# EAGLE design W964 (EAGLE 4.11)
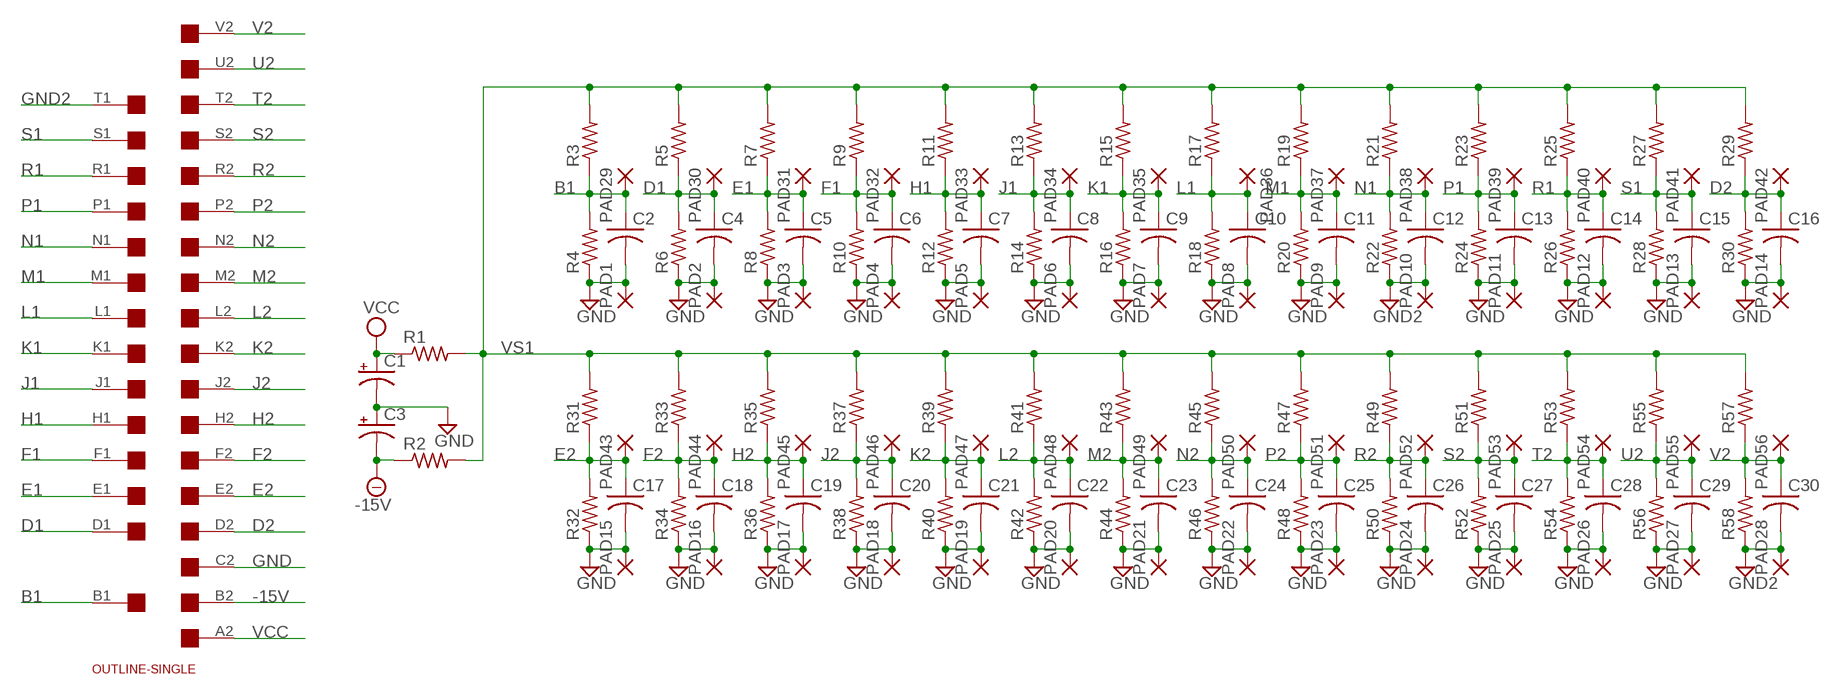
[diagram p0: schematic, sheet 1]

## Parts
C1  CPOL-USE22-6AXIAL  [E22-6]
C2  C-US050-025X075  [C050-025X075]
C3  CPOL-USE22-6AXIAL  [E22-6]
C4  C-US050-025X075  [C050-025X075]
C5  C-US050-025X075  [C050-025X075]
C6  C-US050-025X075  [C050-025X075]
C7  C-US050-025X075  [C050-025X075]
C8  C-US050-025X075  [C050-025X075]
C9  C-US050-025X075  [C050-025X075]
C10  C-US050-025X075  [C050-025X075]
C11  C-US050-025X075  [C050-025X075]
C12  C-US050-025X075  [C050-025X075]
C13  C-US050-025X075  [C050-025X075]
C14  C-US050-025X075  [C050-025X075]
C15  C-US050-025X075  [C050-025X075]
C16  C-US050-025X075  [C050-025X075]
C17  C-US050-025X075  [C050-025X075]
C18  C-US050-025X075  [C050-025X075]
C19  C-US050-025X075  [C050-025X075]
C20  C-US050-025X075  [C050-025X075]
C21  C-US050-025X075  [C050-025X075]
C22  C-US050-025X075  [C050-025X075]
C23  C-US050-025X075  [C050-025X075]
C24  C-US050-025X075  [C050-025X075]
C25  C-US050-025X075  [C050-025X075]
C26  C-US050-025X075  [C050-025X075]
C27  C-US050-025X075  [C050-025X075]
C28  C-US050-025X075  [C050-025X075]
C29  C-US050-025X075  [C050-025X075]
C30  C-US050-025X075  [C050-025X075]
PAD1  1,6/0,9  [1,6/0,9]
PAD2  1,6/0,9  [1,6/0,9]
PAD3  1,6/0,9  [1,6/0,9]
PAD4  1,6/0,9  [1,6/0,9]
PAD5  1,6/0,9  [1,6/0,9]
PAD6  1,6/0,9  [1,6/0,9]
PAD7  1,6/0,9  [1,6/0,9]
PAD8  1,6/0,9  [1,6/0,9]
PAD9  1,6/0,9  [1,6/0,9]
PAD10  1,6/0,9  [1,6/0,9]
PAD11  1,6/0,9  [1,6/0,9]
PAD12  1,6/0,9  [1,6/0,9]
PAD13  1,6/0,9  [1,6/0,9]
PAD14  1,6/0,9  [1,6/0,9]
PAD15  1,6/0,9  [1,6/0,9]
PAD16  1,6/0,9  [1,6/0,9]
PAD17  1,6/0,9  [1,6/0,9]
PAD18  1,6/0,9  [1,6/0,9]
PAD19  1,6/0,9  [1,6/0,9]
PAD20  1,6/0,9  [1,6/0,9]
PAD21  1,6/0,9  [1,6/0,9]
PAD22  1,6/0,9  [1,6/0,9]
PAD23  1,6/0,9  [1,6/0,9]
PAD24  1,6/0,9  [1,6/0,9]
PAD25  1,6/0,9  [1,6/0,9]
PAD26  1,6/0,9  [1,6/0,9]
PAD27  1,6/0,9  [1,6/0,9]
PAD28  1,6/0,9  [1,6/0,9]
PAD29  1,6/0,9  [1,6/0,9]
PAD30  1,6/0,9  [1,6/0,9]
PAD31  1,6/0,9  [1,6/0,9]
PAD32  1,6/0,9  [1,6/0,9]
PAD33  1,6/0,9  [1,6/0,9]
PAD34  1,6/0,9  [1,6/0,9]
PAD35  1,6/0,9  [1,6/0,9]
PAD36  1,6/0,9  [1,6/0,9]
PAD37  1,6/0,9  [1,6/0,9]
PAD38  1,6/0,9  [1,6/0,9]
PAD39  1,6/0,9  [1,6/0,9]
PAD40  1,6/0,9  [1,6/0,9]
PAD41  1,6/0,9  [1,6/0,9]
PAD42  1,6/0,9  [1,6/0,9]
PAD43  1,6/0,9  [1,6/0,9]
PAD44  1,6/0,9  [1,6/0,9]
PAD45  1,6/0,9  [1,6/0,9]
PAD46  1,6/0,9  [1,6/0,9]
PAD47  1,6/0,9  [1,6/0,9]
PAD48  1,6/0,9  [1,6/0,9]
PAD49  1,6/0,9  [1,6/0,9]
PAD50  1,6/0,9  [1,6/0,9]
PAD51  1,6/0,9  [1,6/0,9]
PAD52  1,6/0,9  [1,6/0,9]
PAD53  1,6/0,9  [1,6/0,9]
PAD54  1,6/0,9  [1,6/0,9]
PAD55  1,6/0,9  [1,6/0,9]
PAD56  1,6/0,9  [1,6/0,9]
R1  R-US_0207/10  [0207/10]
R2  R-US_0207/10  [0207/10]
R3  R-US_0207/10  [0207/10]
R4  R-US_0207/10  [0207/10]
R5  R-US_0207/10  [0207/10]
R6  R-US_0207/10  [0207/10]
R7  R-US_0207/10  [0207/10]
R8  R-US_0207/10  [0207/10]
R9  R-US_0207/10  [0207/10]
R10  R-US_0207/10  [0207/10]
R11  R-US_0207/10  [0207/10]
R12  R-US_0207/10  [0207/10]
R13  R-US_0207/10  [0207/10]
R14  R-US_0207/10  [0207/10]
R15  R-US_0207/10  [0207/10]
R16  R-US_0207/10  [0207/10]
R17  R-US_0207/10  [0207/10]
R18  R-US_0207/10  [0207/10]
R19  R-US_0207/10  [0207/10]
R20  R-US_0207/10  [0207/10]
R21  R-US_0207/10  [0207/10]
R22  R-US_0207/10  [0207/10]
R23  R-US_0207/10  [0207/10]
R24  R-US_0207/10  [0207/10]
R25  R-US_0207/10  [0207/10]
R26  R-US_0207/10  [0207/10]
R27  R-US_0207/10  [0207/10]
R28  R-US_0207/10  [0207/10]
R29  R-US_0207/10  [0207/10]
R30  R-US_0207/10  [0207/10]
R31  R-US_0207/10  [0207/10]
R32  R-US_0207/10  [0207/10]
R33  R-US_0207/10  [0207/10]
R34  R-US_0207/10  [0207/10]
R35  R-US_0207/10  [0207/10]
R36  R-US_0207/10  [0207/10]
R37  R-US_0207/10  [0207/10]
R38  R-US_0207/10  [0207/10]
R39  R-US_0207/10  [0207/10]
R40  R-US_0207/10  [0207/10]
R41  R-US_0207/10  [0207/10]
R42  R-US_0207/10  [0207/10]
R43  R-US_0207/10  [0207/10]
R44  R-US_0207/10  [0207/10]
R45  R-US_0207/10  [0207/10]
R46  R-US_0207/10  [0207/10]
R47  R-US_0207/10  [0207/10]
R48  R-US_0207/10  [0207/10]
R49  R-US_0207/10  [0207/10]
R50  R-US_0207/10  [0207/10]
R51  R-US_0207/10  [0207/10]
R52  R-US_0207/10  [0207/10]
R53  R-US_0207/10  [0207/10]
R54  R-US_0207/10  [0207/10]
R55  R-US_0207/10  [0207/10]
R56  R-US_0207/10  [0207/10]
R57  R-US_0207/10  [0207/10]
R58  R-US_0207/10  [0207/10]
U$1  EDGE-2CONNECTOR  [EDGE-CON2]
U$2  OUTLINE-SINGLE  [SINGLE]

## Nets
-15V [power]: C3.- R2.1 U$1.B2
B1: C2.1 PAD29.1(P) R3.1 R4.2 U$1.B1
D1: C4.1 PAD30.1(P) R5.1 R6.2 U$1.D1
D2: C16.1 PAD42.1(P) R29.1 R30.2 U$1.D2
E1: C5.1 PAD31.1(P) R7.1 R8.2 U$1.E1
E2: C17.1 PAD43.1(P) R31.1 R32.2 U$1.E2
F1: C6.1 PAD32.1(P) R9.1 R10.2 U$1.F1
F2: C18.1 PAD44.1(P) R33.1 R34.2 U$1.F2
GND [power]: C1.- C2.2 C3.+ C4.2 C5.2 C6.2 C7.2 C8.2 C9.2 C10.2 C11.2 C13.2 C14.2 C15.2 C16.2 C17.2 C18.2 C19.2 C20.2 C21.2 C22.2 C23.2 C24.2 C25.2 C26.2 C27.2 C28.2 C29.2 PAD1.1(P) PAD2.1(P) PAD3.1(P) PAD4.1(P) PAD5.1(P) PAD6.1(P) PAD7.1(P) PAD8.1(P) PAD9.1(P) PAD11.1(P) PAD12.1(P) PAD13.1(P) PAD14.1(P) PAD15.1(P) PAD16.1(P) PAD17.1(P) PAD18.1(P) PAD19.1(P) PAD20.1(P) PAD21.1(P) PAD22.1(P) PAD23.1(P) PAD24.1(P) PAD25.1(P) PAD26.1(P) PAD27.1(P) R4.1 R6.1 R8.1 R10.1 R12.1 R14.1 R16.1 R18.1 R20.1 R24.1 R26.1 R28.1 R30.1 R32.1 R34.1 R36.1 R38.1 R40.1 R42.1 R44.1 R46.1 R48.1 R50.1 R52.1 R54.1 R56.1 U$1.C2
GND2 [power]: C12.2 C30.2 PAD10.1(P) PAD28.1(P) R22.1 R58.1 U$1.T1
H1: C7.1 PAD33.1(P) R11.1 R12.2 U$1.H1
H2: C19.1 PAD45.1(P) R35.1 R36.2 U$1.H2
J1: C8.1 PAD34.1(P) R13.1 R14.2 U$1.J1
J2: C20.1 PAD46.1(P) R37.1 R38.2 U$1.J2
K1: C9.1 PAD35.1(P) R15.1 R16.2 U$1.K1
K2: C21.1 PAD47.1(P) R39.1 R40.2 U$1.K2
L1: C10.1 PAD36.1(P) R17.1 R18.2 U$1.L1
L2: C22.1 PAD48.1(P) R41.1 R42.2 U$1.L2
M1: C11.1 PAD37.1(P) R19.1 R20.2 U$1.M1
M2: C23.1 PAD49.1(P) R43.1 R44.2 U$1.M2
N1: C12.1 PAD38.1(P) R21.1 R22.2 U$1.N1
N2: C24.1 PAD50.1(P) R45.1 R46.2 U$1.N2
P1: C13.1 PAD39.1(P) R23.1 R24.2 U$1.P1
P2: C25.1 PAD51.1(P) R47.1 R48.2 U$1.P2
R1: C14.1 PAD40.1(P) R25.1 R26.2 U$1.R1
R2: C26.1 PAD52.1(P) R49.1 R50.2 U$1.R2
S1: C15.1 PAD41.1(P) R27.1 R28.2 U$1.S1
S2: C27.1 PAD53.1(P) R51.1 R52.2 U$1.S2
T2: C28.1 PAD54.1(P) R53.1 R54.2 U$1.T2
U2: C29.1 PAD55.1(P) R55.1 R56.2 U$1.U2
V2: C30.1 PAD56.1(P) R57.1 R58.2 U$1.V2
VCC [power]: C1.+ R1.1 U$1.A2
VS1: R1.2 R2.2 R3.2 R5.2 R7.2 R9.2 R11.2 R13.2 R15.2 R17.2 R19.2 R21.2 R23.2 R25.2 R27.2 R29.2 R31.2 R33.2 R35.2 R37.2 R39.2 R41.2 R43.2 R45.2 R47.2 R49.2 R51.2 R53.2 R55.2 R57.2
Unconnected: U$1.A1 U$1.C1 U$1.U1 U$1.V1

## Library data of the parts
C1 C3 = rcl:CPOL-US: POLARIZED CAPACITOR, American symbol
C2 C4-C30 = rcl:C-US: CAPACITOR, American symbol
PAD1-PAD56 = wirepad:1,6/0,9: THROUGH-HOLE PAD
R1-R58 = rcl:R-US_: RESISTOR, American symbol
U$1 = dec-con:EDGE-2: Double-Sided DEC edge connector.
U$2 = dec-con:OUTLINE-*: Board outlines for DEC boards.

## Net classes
1 power: width 0.508 mm

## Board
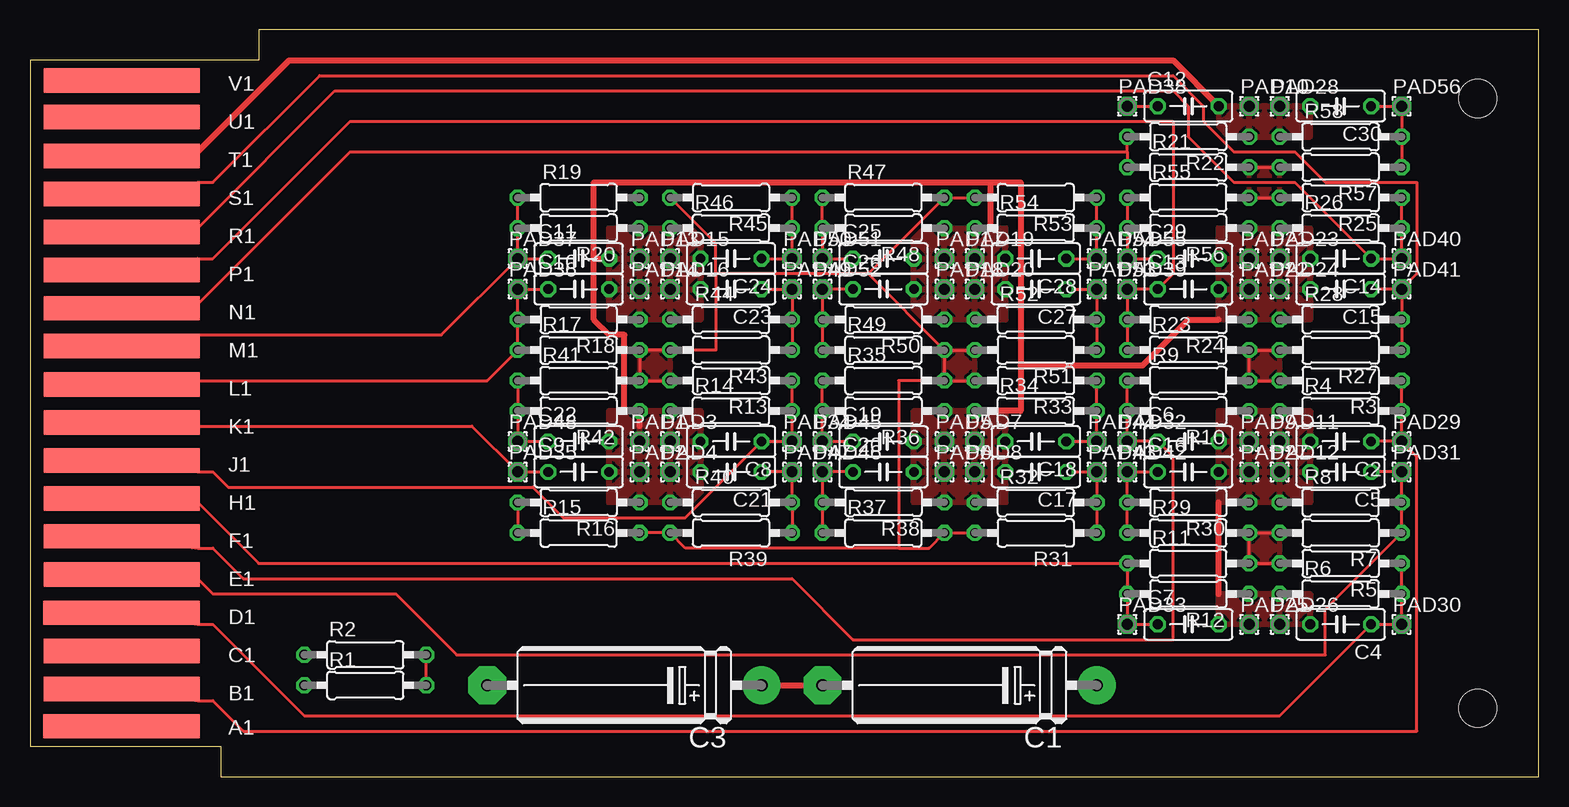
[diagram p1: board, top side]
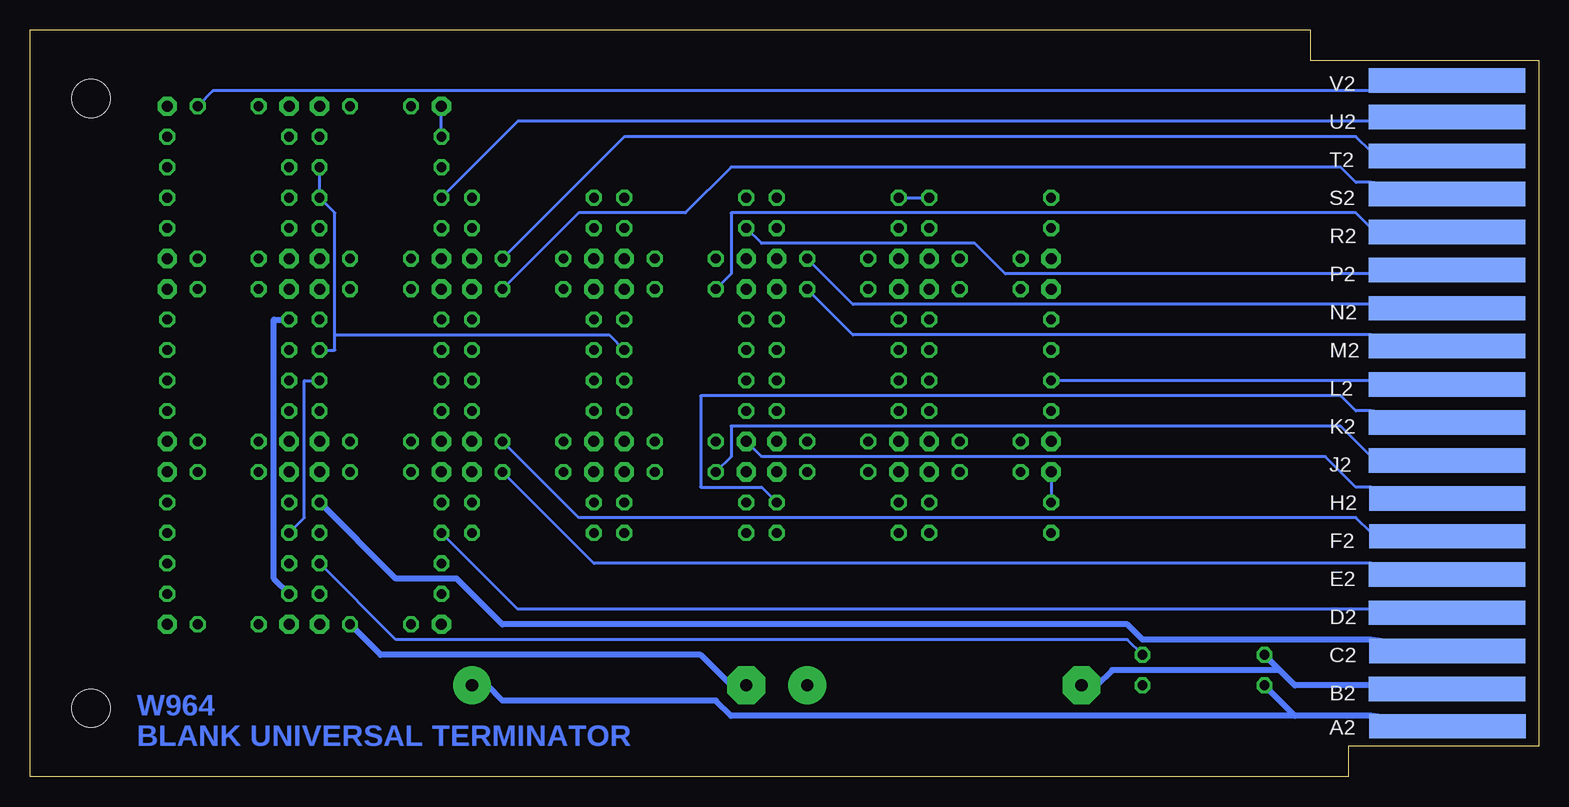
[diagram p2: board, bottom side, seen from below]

Size 125.73 x 62.23 mm. Coordinates in mm from the lower left corner, seen from the top.
Copper layers (1*16): Top 0.035mm / dielectric 1.5mm / Bottom 0.035mm
Design rules "10mils": minimum track width 10mil, minimum drill 24mil, track to track 10mil, track to pad 10mil, pad to pad 10mil, via to via 10mil, smd to smd 10mil, copper to edge 25mil, drill to drill 10mil, minimum pad ring 10mil, minimum via ring 8mil, stop-mask expansion 0mil, vias tented up to drill 0mil, thermal gap 10mil

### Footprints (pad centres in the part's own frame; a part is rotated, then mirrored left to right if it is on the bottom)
E22-6 = drill 1.016 pad 3.15 round: + -11.43,0 | drill 1.016 pad 3.15 octagon: - 11.43,0
C050-025X075 = drill 0.813 octagon: 1 -2.54,0; 2 2.54,0
1,6/0,9 = drill 0.914 pad 1.6 octagon: 1 0,0
0207/10 = drill 0.813 octagon: 1 -5.08,0; 2 5.08,0
EDGE-CON2 = smd 13.017 x 2.032: A1 7.633,4.207; B1 7.639,7.327; C1 7.636,10.489; D1 7.633,13.665; E1 7.642,16.84; F1 7.642,20.041; H1 7.642,23.19; J1 7.642,26.34; K1 7.642,29.515; L1 7.642,32.69; M1 7.642,35.89; N1 7.642,39.04; P1 7.642,42.24; R1 7.642,45.39; S1 7.642,48.565; T1 7.642,51.74; U1 7.642,54.966; V1 7.642,58.026 | smd 13.017 x 2.032 bottom: A2 7.614,4.207; B2 7.642,7.328; C2 7.617,10.49; D2 7.642,13.665; E2 7.642,16.84; F2 7.617,20.041; H2 7.617,23.19; J2 7.642,26.34; K2 7.642,29.515; L2 7.642,32.69; M2 7.642,35.89; N2 7.642,39.04; P2 7.642,42.24; R2 7.642,45.39; S2 7.642,48.565; T2 7.642,51.74; U2 7.642,54.966; V2 7.642,58.026
SINGLE = hole 3.175: 120.65,56.515; 120.65,5.715

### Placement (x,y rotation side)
C1  77.47,7.62 180 top
C2  109.22,27.94 180 top
C3  49.53,7.62 180 top
C4  109.22,12.7 180 top
C5  109.22,25.4 180 top
C6  96.52,27.94 0 top
C7  96.52,12.7 0 top
C8  58.42,27.94 180 top
C9  45.72,25.4 0 top
C10  45.72,40.64 0 top
C11  45.72,43.18 0 top
C12  96.52,55.88 0 top
C13  96.52,40.64 0 top
C14  109.22,43.18 180 top
C15  109.22,40.64 180 top
C16  96.52,25.4 0 top
C17  83.82,25.4 180 top
C18  83.82,27.94 180 top
C19  71.12,27.94 0 top
C20  71.12,25.4 0 top
C21  58.42,25.4 180 top
C22  45.72,27.94 0 top
C23  58.42,40.64 180 top
C24  58.42,43.18 180 top
C25  71.12,43.18 0 top
C26  71.12,40.64 0 top
C27  83.82,40.64 180 top
C28  83.82,43.18 180 top
C29  96.52,43.18 0 top
C30  109.22,55.88 180 top
PAD1  50.8,27.94 0 top
PAD2  50.8,25.4 0 top
PAD3  53.34,27.94 0 top
PAD4  53.34,25.4 0 top
PAD5  76.2,27.94 0 top
PAD6  76.2,25.4 0 top
PAD7  78.74,27.94 0 top
PAD8  78.74,25.4 0 top
PAD9  101.6,27.94 0 top
PAD10  101.6,55.88 0 top
PAD11  104.14,27.94 0 top
PAD12  104.14,25.4 0 top
PAD13  50.8,43.18 0 top
PAD14  50.8,40.64 0 top
PAD15  53.34,43.18 0 top
PAD16  53.34,40.64 0 top
PAD17  76.2,43.18 0 top
PAD18  76.2,40.64 0 top
PAD19  78.74,43.18 0 top
PAD20  78.74,40.64 0 top
PAD21  101.6,43.18 0 top
PAD22  101.6,40.64 0 top
PAD23  104.14,43.18 0 top
PAD24  104.14,40.64 0 top
PAD25  101.6,12.7 0 top
PAD26  104.14,12.7 0 top
PAD27  101.6,25.4 0 top
PAD28  104.14,55.88 0 top
PAD29  114.3,27.94 0 top
PAD30  114.3,12.7 0 top
PAD31  114.3,25.4 0 top
PAD32  91.44,27.94 0 top
PAD33  91.44,12.7 0 top
PAD34  63.5,27.94 0 top
PAD35  40.64,25.4 0 top
PAD36  40.64,40.64 0 top
PAD37  40.64,43.18 0 top
PAD38  91.44,55.88 0 top
PAD39  91.44,40.64 0 top
PAD40  114.3,43.18 0 top
PAD41  114.3,40.64 0 top
PAD42  91.44,25.4 0 top
PAD43  88.9,25.4 0 top
PAD44  88.9,27.94 0 top
PAD45  66.04,27.94 0 top
PAD46  66.04,25.4 0 top
PAD47  63.5,25.4 0 top
PAD48  40.64,27.94 0 top
PAD49  63.5,40.64 0 top
PAD50  63.5,43.18 0 top
PAD51  66.04,43.18 0 top
PAD52  66.04,40.64 0 top
PAD53  88.9,40.64 0 top
PAD54  88.9,43.18 0 top
PAD55  91.44,43.18 0 top
PAD56  114.3,55.88 0 top
R1  27.94,7.62 0 top
R2  27.94,10.16 0 top
R3  109.22,33.02 180 top
R4  109.22,30.48 0 top
R5  109.22,17.78 180 top
R6  109.22,15.24 0 top
R7  109.22,20.32 180 top
R8  109.22,22.86 0 top
R9  96.52,33.02 0 top
R10  96.52,30.48 180 top
R11  96.52,17.78 0 top
R12  96.52,15.24 180 top
R13  58.42,33.02 180 top
R14  58.42,30.48 0 top
R15  45.72,20.32 0 top
R16  45.72,22.86 180 top
R17  45.72,35.56 0 top
R18  45.72,38.1 180 top
R19  45.72,48.26 0 top
R20  45.72,45.72 180 top
R21  96.52,50.8 0 top
R22  96.52,53.34 180 top
R23  96.52,35.56 0 top
R24  96.52,38.1 180 top
R25  109.22,48.26 180 top
R26  109.22,45.72 0 top
R27  109.22,35.56 180 top
R28  109.22,38.1 0 top
R29  96.52,20.32 0 top
R30  96.52,22.86 180 top
R31  83.82,20.32 180 top
R32  83.82,22.86 0 top
R33  83.82,33.02 180 top
R34  83.82,30.48 0 top
R35  71.12,33.02 0 top
R36  71.12,30.48 180 top
R37  71.12,20.32 0 top
R38  71.12,22.86 180 top
R39  58.42,20.32 180 top
R40  58.42,22.86 0 top
R41  45.72,33.02 0 top
R42  45.72,30.48 180 top
R43  58.42,35.56 180 top
R44  58.42,38.1 0 top
R45  58.42,48.26 180 top
R46  58.42,45.72 0 top
R47  71.12,48.26 0 top
R48  71.12,45.72 180 top
R49  71.12,35.56 0 top
R50  71.12,38.1 180 top
R51  83.82,35.56 180 top
R52  83.82,38.1 0 top
R53  83.82,48.26 180 top
R54  83.82,45.72 0 top
R55  96.52,48.26 0 top
R56  96.52,45.72 180 top
R57  109.22,50.8 180 top
R58  109.22,53.34 0 top
U$1  0,0 0 top
U$2  0,0 0 top

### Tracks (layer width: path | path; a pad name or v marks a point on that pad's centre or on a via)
-15V
  Bottom 0.508: 21.59,8.89 20.32,7.62 13.97,7.62 U$1.B2 | 21.59,8.89 R2.1 | 21.59,8.89 35.56,8.89 36.83,7.62 C3.-
B1
  Top 0.254: R3.1 R4.2 PAD29.1 | PAD29.1 C2.1 | PAD29.1 115.57,26.67 115.57,3.81 17.78,3.81 15.24,6.35 13.97,6.35 U$1.B1
D1
  Top 0.254: R5.1 R6.2 PAD30.1 C4.1 104.14,5.08 22.86,5.08 15.24,12.7 13.97,12.7 U$1.D1
D2
  Top 0.254: R29.1 R30.2 PAD42.1 C16.1
  Bottom 0.254: R29.1 85.09,13.97 13.97,13.97 U$1.D2
E1
  Top 0.254: C5.1 PAD31.1 R8.2 R7.1 107.95,13.97 107.95,10.16 35.56,10.16 30.48,15.24 15.24,15.24 13.97,16.51 U$1.E1
E2
  Top 0.254: R31.1 R32.2 PAD43.1 C17.1
  Bottom 0.254: C17.1 78.74,17.78 13.97,17.78 U$1.E2
F1
  Top 0.254: R9.1 R10.2 PAD32.1 C6.1 95.25,26.67 95.25,11.43 68.58,11.43 63.5,16.51 17.78,16.51 15.24,19.05 13.97,19.05 U$1.F1
F2
  Top 0.254: R33.1 R34.2 PAD44.1 C18.1
  Bottom 0.254: C18.1 80.01,21.59 15.24,21.59 13.97,20.32 U$1.F2
GND
  Top 0.508: 99.06,15.24 99.06,22.86 | C3.+ C1.- | 46.99,43.18 46.99,38.1 48.26,36.83 49.53,36.83 49.53,30.48 R42.1 50.8,29.21 | 46.99,43.18 46.99,49.53 80.01,49.53 | 80.01,49.53 80.01,45.72 | 46.99,43.18 C11.2 | 80.01,49.53 82.55,49.53 82.55,34.29 | 82.55,34.29 92.71,34.29 96.52,38.1 99.06,38.1 | 82.55,34.29 82.55,30.48 R34.1
  Bottom 0.508: R6.1 105.41,16.51 105.41,38.1 R28.1 | C7.2 96.52,10.16 69.85,10.16 67.31,7.62 C1.- | R30.1 95.25,16.51 90.17,16.51 86.36,12.7 34.29,12.7 33.02,11.43 13.97,11.43 U$1.C2
  pour Top: 48.26,30.48 55.88,30.48 55.88,22.86 48.26,22.86
  pour Top: 48.26,45.72 55.88,45.72 55.88,38.1 48.26,38.1
  pour Top: 73.66,45.72 81.28,45.72 81.28,38.1 73.66,38.1
  pour Top: 73.66,30.48 81.28,30.48 81.28,22.86 73.66,22.86
  pour Top: 99.06,30.48 106.68,30.48 106.68,22.86 99.06,22.86
  pour Top: 99.06,45.72 106.68,45.72 106.68,38.1 99.06,38.1
  pour Top: 99.06,12.7 99.06,15.24 106.68,15.24 106.68,12.7
GND2
  Top 0.508: C12.2 95.25,59.69 21.59,59.69 13.97,52.07 U$1.T1
  pour Top: 99.06,53.34 106.68,53.34 106.68,55.88 99.06,55.88
H1
  Top 0.254: C7.1 PAD33.1 R12.2 R11.1 19.05,17.78 13.97,22.86 U$1.H1
H2
  Top 0.254: R35.1 R36.2 PAD45.1 C19.1
  Bottom 0.254: PAD45.1 64.77,26.67 17.78,26.67 15.24,24.13 13.97,24.13 U$1.H2
J1
  Top 0.254: R13.1 R14.2 PAD34.1 C8.1 54.61,21.59 44.45,21.59 41.91,24.13 16.51,24.13 15.24,25.4 13.97,25.4 U$1.J1
J2
  Top 0.254: R37.1 R38.2 PAD46.1 C20.1
  Bottom 0.254: C20.1 67.31,26.67 67.31,29.21 16.51,29.21 13.97,26.67 U$1.J2
K1
  Top 0.254: R16.2 R15.1 | C9.1 PAD35.1 36.83,29.21 13.97,29.21 U$1.K1
  Bottom 0.254: PAD35.1 R16.2
K2
  Top 0.254: R39.1 R40.2 PAD47.1 C21.1
  Bottom 0.254: R40.2 64.77,24.13 69.85,24.13 69.85,31.75 16.51,31.75 15.24,30.48 13.97,30.48 U$1.K2
L1
  Top 0.254: C10.1 PAD36.1 R18.2 R17.1 38.1,33.02 13.97,33.02 U$1.L1
L2
  Top 0.254: R41.1 R42.2 PAD48.1 C22.1
  Bottom 0.254: R41.1 13.97,33.02 U$1.L2
M1
  Top 0.254: R19.1 R20.2 PAD37.1 | PAD37.1 C11.1 | PAD37.1 34.29,36.83 13.97,36.83 U$1.M1
M2
  Top 0.254: R43.1 R44.2 PAD49.1 C23.1
  Bottom 0.254: C23.1 57.15,36.83 13.97,36.83 U$1.M2
N1
  Top 0.254: 91.44,52.07 R22.2 | 91.44,52.07 R21.1 | PAD38.1 C12.1 | 91.44,52.07 26.67,52.07 13.97,39.37 U$1.N1
  Bottom 0.254: R22.2 PAD38.1
N2
  Top 0.254: R45.1 R46.2 PAD50.1 C24.1
  Bottom 0.254: C24.1 57.15,39.37 13.97,39.37 U$1.N2
P1
  Top 0.254: R23.1 R24.2 PAD39.1 C13.1 95.25,41.91 95.25,54.61 26.67,54.61 15.24,43.18 13.97,43.18 U$1.P1
P2
  Top 0.254: R47.1 R48.2 PAD51.1 C25.1
  Bottom 0.254: R48.2 64.77,44.45 46.99,44.45 44.45,41.91 13.97,41.91 U$1.P2
R1
  Top 0.254: R25.1 R26.2 PAD40.1 C14.1 105.41,49.53 100.33,49.53 96.52,53.34 96.52,55.88 95.25,57.15 25.4,57.15 13.97,45.72 U$1.R1
R2
  Top 0.254: R49.1 R50.2 PAD52.1 C26.1
  Bottom 0.254: C26.1 67.31,41.91 67.31,46.99 15.24,46.99 13.97,45.72 U$1.R2
S1
  Top 0.254: R27.1 R28.2 PAD41.1 | PAD41.1 C15.1 | PAD41.1 115.57,41.91 115.57,49.53 107.95,49.53 105.41,52.07 100.33,52.07 97.79,54.61 97.79,55.88 95.25,58.42 24.13,58.42 15.24,49.53 13.97,49.53 U$1.S1
S2
  Top 0.254: R51.1 R52.2 PAD53.1 C27.1
  Bottom 0.254: C27.1 80.01,46.99 71.12,46.99 67.31,50.8 16.51,50.8 15.24,49.53 13.97,49.53 U$1.S2
T2
  Top 0.254: R53.1 R54.2 PAD54.1 C28.1
  Bottom 0.254: C28.1 76.2,53.34 15.24,53.34 13.97,52.07 U$1.T2
U2
  Top 0.254: R55.1 R56.2 PAD55.1 C29.1
  Bottom 0.254: R55.1 85.09,54.61 13.97,54.61 U$1.U2
V2
  Top 0.254: R57.1 R58.2 PAD56.1 C30.1
  Bottom 0.254: C30.1 110.49,57.15 13.97,57.15 U$1.V2
VCC
  Bottom 0.508: 20.32,5.08 R1.1 | 20.32,5.08 13.97,5.08 U$1.A2 | 20.32,5.08 67.31,5.08 68.58,6.35 86.36,6.35 87.63,7.62 C1.+
VS1
  Top 0.254: R1.2 R2.2 | R5.2 R11.2 R29.2 R7.2 | R15.2 R39.2 54.61,19.05 72.39,19.05 | R31.2 R37.2 74.93,19.05 72.39,19.05 | R55.2 R25.2 | R21.2 R57.2 | R3.2 R9.2 R23.2 R27.2 | R49.2 R35.2 | R35.2 R33.2 | R49.2 R51.2 | R53.2 R47.2 69.85,41.91 | R13.2 R41.2 R17.2 R43.2 57.15,35.56 57.15,41.91 | R45.2 57.15,44.45 57.15,41.91 | 69.85,41.91 57.15,41.91 | R49.2 69.85,41.91 | 72.39,19.05 72.39,33.02 R35.2
  Bottom 0.254: R2.2 34.29,11.43 95.25,11.43 R11.2 | R21.2 R55.2 100.33,46.99 100.33,36.83 | R45.2 R19.2 | 100.33,36.83 100.33,35.56 R23.2 | R7.2 102.87,21.59 102.87,33.02 R9.2 | R49.2 77.47,36.83 100.33,36.83
  pour Top: 50.8,35.56 53.34,35.56 53.34,33.02 50.8,33.02
  pour Top: 76.2,35.56 78.74,35.56 78.74,33.02 76.2,33.02
  pour Top: 101.6,35.56 104.14,35.56 104.14,33.02 101.6,33.02
  pour Top: 101.6,20.32 104.14,20.32 104.14,17.78 101.6,17.78
  pour Top: 101.6,50.8 104.14,50.8 104.14,48.26 101.6,48.26

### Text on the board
Bottom: W964 | BLANK UNIVERSAL TERMINATOR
